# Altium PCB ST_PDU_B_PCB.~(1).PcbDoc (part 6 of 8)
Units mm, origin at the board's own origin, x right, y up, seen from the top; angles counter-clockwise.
Board outline 200 x 200 mm, 6 copper layers (Top Layer, Layer 1, Layer 2, Layer 3, Layer 4, Bottom Layer), stack 3.194 mm thick; 894 components, 723 nets, 3233 pads, 4067 vias.
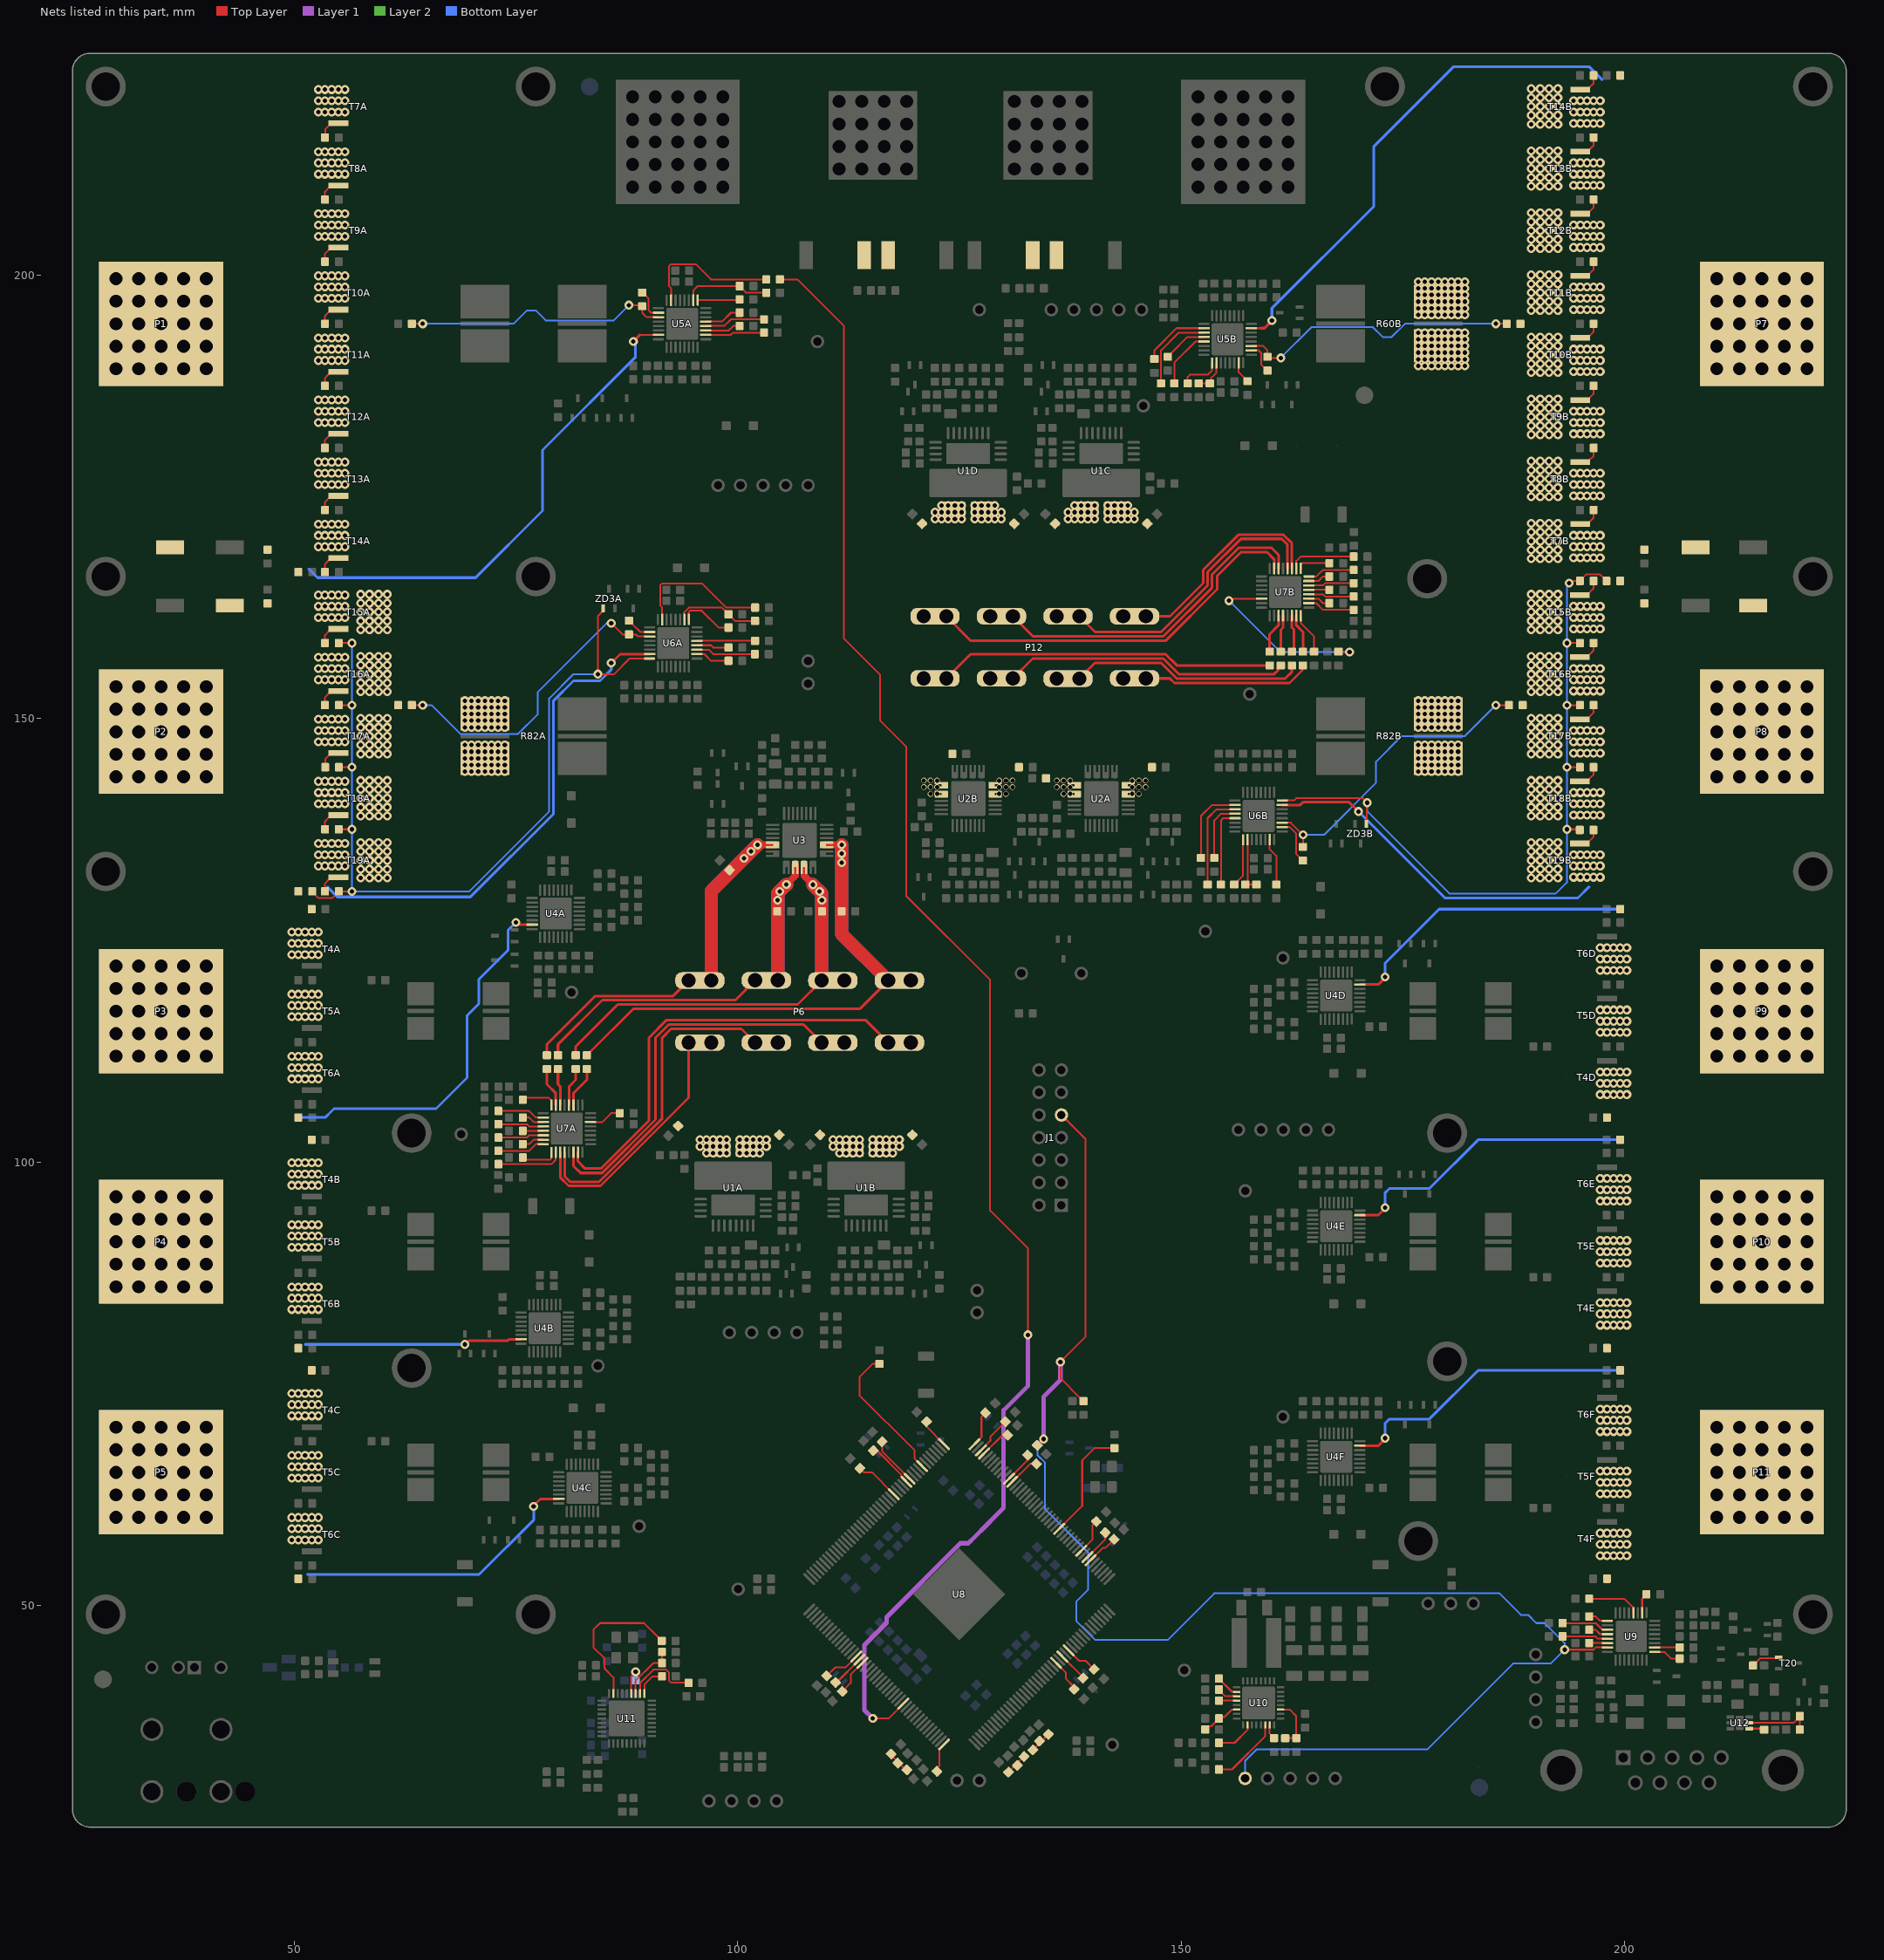
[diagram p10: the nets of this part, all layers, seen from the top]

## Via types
v1: diameter 0.65/1/1/1/1/0.65 (per signal layer), hole 0.5, Top Layer to Bottom Layer, 3739 vias
v2: diameter 0.65/1/1/1/1/0.65 (per signal layer), hole 0.5, Top Layer to Bottom Layer, tented both sides, 296 vias
v3: diameter 0.65, hole 0.5, Top Layer to Bottom Layer, 32 vias

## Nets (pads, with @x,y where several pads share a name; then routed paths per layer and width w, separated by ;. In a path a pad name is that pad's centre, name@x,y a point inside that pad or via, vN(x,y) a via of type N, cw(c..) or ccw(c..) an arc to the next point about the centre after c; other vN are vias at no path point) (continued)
NetR60B_1: R60B.1 R73B.2 T7B.D T8B.D T9B.D T10B.D T11B.D T12B.D T13B.D T14B.D
  other v1: 189.5,168 190.5,168 191.5,168 192.5,168 189.5,169 190.5,169 191.5,169 192.5,169 189.5,170 190.5,170 191.5,170 192.5,170 189.5,171 190.5,171 191.5,171 192.5,171 189.5,172 190.5,172 191.5,172 192.5,172 189.5,175 190.5,175 191.5,175 192.5,175 189.5,176 190.5,176 191.5,176 192.5,176 189.5,177 190.5,177 191.5,177 192.5,177 189.5,178 190.5,178 191.5,178 192.5,178 189.5,179 190.5,179 191.5,179 192.5,179 189.5,182 190.5,182 191.5,182 192.5,182 189.5,183 190.5,183 191.5,183 192.5,183 189.5,184 190.5,184 191.5,184 192.5,184 189.5,185 190.5,185 191.5,185 192.5,185 189.5,186 190.5,186 191.5,186 192.5,186 189.5,189 190.5,189 191.5,189 192.5,189 189.5,190 190.5,190 191.5,190 192.5,190 176.75,190.5 177.5,190.5 178.25,190.5 179,190.5 179.75,190.5 180.5,190.5 181.25,190.5 189.5,191 190.5,191 191.5,191 192.5,191 176.75,191.25 177.5,191.25 178.25,191.25 179,191.25 179.75,191.25 180.5,191.25 181.25,191.25 176.75,192 177.5,192 178.25,192 179,192 179.75,192 180.5,192 181.25,192 189.5,192 190.5,192 191.5,192 192.5,192 176.75,192.75 177.5,192.75 178.25,192.75 179,192.75 179.75,192.75 180.5,192.75 181.25,192.75 189.5,193 190.5,193 191.5,193 192.5,193 176.75,193.5 177.5,193.5 178.25,193.5 179,193.5 179.75,193.5 180.5,193.5 181.25,193.5 176.75,195.5 177.5,195.5 178.25,195.5 179,195.5 179.75,195.5 180.5,195.5 181.25,195.5 189.5,196 190.5,196 191.5,196 192.5,196 176.75,196.25 177.5,196.25 178.25,196.25 179,196.25 179.75,196.25 180.5,196.25 181.25,196.25 176.75,197 177.5,197 178.25,197 179,197 179.75,197 180.5,197 181.25,197 189.5,197 190.5,197 191.5,197 192.5,197 176.75,197.75 177.5,197.75 178.25,197.75 179,197.75 179.75,197.75 180.5,197.75 181.25,197.75 189.5,198 190.5,198 191.5,198 192.5,198 176.75,198.5 177.5,198.5 178.25,198.5 179,198.5 179.75,198.5 180.5,198.5 181.25,198.5 189.5,199 190.5,199 191.5,199 192.5,199 189.5,200 190.5,200 191.5,200 192.5,200 189.5,203 190.5,203 191.5,203 192.5,203 189.5,204 190.5,204 191.5,204 192.5,204 189.5,205 190.5,205 191.5,205 192.5,205 189.5,206 190.5,206 191.5,206 192.5,206 189.5,207 190.5,207 191.5,207 192.5,207 189.5,210 190.5,210 191.5,210 192.5,210 189.5,211 190.5,211 191.5,211 192.5,211 189.5,212 190.5,212 191.5,212 192.5,212 189.5,213 190.5,213 191.5,213 192.5,213 189.5,214 190.5,214 191.5,214 192.5,214 189.5,217 190.5,217 191.5,217 192.5,217 189.5,218 190.5,218 191.5,218 192.5,218 189.5,219 190.5,219 191.5,219 192.5,219 189.5,220 190.5,220 191.5,220 192.5,220 189.5,221 190.5,221 191.5,221 192.5,221
  other v2: 176.75,189.75 177.5,189.75 178.25,189.75 179,189.75 179.75,189.75 180.5,189.75 181.25,189.75 182,189.75 182,190.5 182,191.25 182,192 182,192.75 182,193.5 182,195.5 182,196.25 182,197 182,197.75 182,198.5 176.75,199.25 177.5,199.25 178.25,199.25 179,199.25 179.75,199.25 180.5,199.25 181.25,199.25 182,199.25
NetR61A_2: R61A.2 T7A.G | length 2.7
  Top Layer w0.2: R61A.2@53.475,215.5 53.5,215.525 53.5,216.417 54.178,217.095 T7A.G@54.978,217.095
NetR61B_2: R61B.2 T7B.G | length 2.7
  Top Layer w0.2: T7B.G@195.022,171.905 195.822,171.905 196.5,172.583 196.5,173.475 R61B.2@196.525,173.5
NetR62A_2: R62A.2 T8A.G | length 2.7
  Top Layer w0.2: R62A.2@53.475,208.5 53.475,209.392 53.953,209.87 54.178,210.095 T8A.G@54.978,210.095
NetR62B_2: R62B.2 T8B.G | length 2.7
  Top Layer w0.2: T8B.G@195.022,178.905 195.822,178.905 196.047,179.13 196.525,179.608 R62B.2@196.525,180.5
NetR63A_2: R63A.2 T9A.G | length 2.6
  Top Layer w0.2: R63A.2@53.475,201.5 53.475,202.392 53.953,202.87 54.083,203 T9A.G@54.883,203
NetR63B_2: R63B.2 T9B.G | length 2.6
  Top Layer w0.2: T9B.G@195.117,186 195.917,186 196.047,186.13 196.525,186.608 R63B.2@196.525,187.5
NetR65_1: R65.1 U10.22 | length 8.1
  Top Layer w0.2: R65.1@154.275,31.5 155.75,31.5 159.5,35.25 U10.22@159.5,36.523
NetR66A_2: R66A.2 T10A.G | length 2.8
  Top Layer w0.2: R66A.2@53.475,194.5 53.475,195.392 53.703,195.62 54.178,196.095 T10A.G@54.978,196.095 T10A.G@54.883,196
NetR66B_2: R66B.2 T10B.G | length 2.8
  Top Layer w0.2: T10B.G@195.117,193 T10B.G@195.022,192.905 195.822,192.905 196.297,193.38 196.525,193.608 R66B.2@196.525,194.5
NetR67A_1: R67A.1 U5A.2 | length 6.7
  Top Layer w0.2: U5A.2@96.402,193.25 99.25,193.25 99.5,193.5 R67A.1@102.975,193.5
NetR67B_1: R67B.1 U5B.2 | length 7.4
  Top Layer w0.2: R67B.1@147,190.775 147,191.5 149.5,194 U5B.2@152.598,194
NetR68A_1: R68A.1 U5A.3 | length 4
  Top Layer w0.2: U5A.3@96.402,193.75 99,193.75 99.5,194.25 R68A.1@100.225,194.25
NetR68B_1: R68B.1 U5B.3 | length 9.4
  Top Layer w0.2: R68B.1@147.75,187.775 147.75,191.5 149.75,193.5 U5B.3@152.598,193.5
NetR69A_2: R69A.2 U5A.4 | length 6.9
  Top Layer w0.2: U5A.4@96.402,194.25 98.5,194.25 99.25,195 R69A.2@102.975,195
NetR69B_2: R69B.2 U5B.4 | length 5
  Top Layer w0.2: R69B.2@148.5,190.775 148.518,190.775 148.867,191.124 148.867,191.142 150.725,193 U5B.4@152.598,193
NetR70A_1: R70A.1 U5A.5 | length 4.2
  Top Layer w0.2: U5A.5@96.402,194.75 98.25,194.75 99.25,195.75 R70A.1@100.225,195.75
NetR70B_1: R70B.1 U5B.5 | length 6.7
  Top Layer w0.2: R70B.1@149.25,187.775 149.25,190.102 151.648,192.5 U5B.5@152.598,192.5
NetR72A_2: R72A.2 T11A.G | length 2.7
  Top Layer w0.2: R72A.2@53.475,187.5 53.475,188.392 53.703,188.62 54.178,189.095 T11A.G@54.978,189.095
NetR72B_2: R72B.2 T11B.G | length 2.7
  Top Layer w0.2: T11B.G@195.022,199.905 195.822,199.905 196.297,200.38 196.525,200.608 R72B.2@196.525,201.5
NetR73A_1: R73A.1 R76A.2 U5A.19 | length 30.6
  Top Layer w0.2: R73A.1@63.275,194.5 v1(64.5,194.5) ; v1(87.75,196.6) 89.125,196.6 R76A.2@89.25,196.475 89.25,195.75 89.75,195.25 U5A.19@91.098,195.25
  Bottom Layer w0.2: v1(64.5,194.5) 74.75,194.5 76.25,196 77.25,196 78.371,194.879 86.029,194.879 v1(87.75,196.6)
NetR73B_1: R73B.1 R76B.2 U5B.19 | length 32.5
  Top Layer w0.2: U5B.19@157.902,192 159.25,192 159.75,191.5 R76B.2@159.75,190.775 159.875,190.65 v1(161.25,190.65) ; v1(185.5,194.5) R73B.1@186.725,194.5
  Bottom Layer w0.2: v1(161.25,190.65) 164.721,194.121 171.629,194.121 172.75,193 173.75,193 175.25,194.5 v1@185.718,194.5
NetR74A_2: R74A.2 T12A.G | length 2.6
  Top Layer w0.2: R74A.2@53.475,180.5 53.475,181.392 54.083,182 T12A.G@54.883,182
NetR74B_2: R74B.2 T12B.G | length 2.6
  Top Layer w0.2: T12B.G@195.117,207 195.917,207 196.525,207.608 R74B.2@196.525,208.5
NetR75A_2: R75A.2 R78A.1 U5A.10 | length 9.8
  Top Layer w0.2: U5A.10@95,197.152 95,198.25 95.5,198.75 R75A.2@100.225,198.75 ; R75A.2@100.225,198.725 100.925,198.025 103.2,198.025 R78A.1@103.225,198
NetR75B_2: R75B.2 R78B.1 U5B.10 | length 3.9
  Top Layer w0.2: R75B.2@152,187.775 153.025,187.775 R78B.1@153.25,187.775 153.408,187.933 153.408,188.408 154,189 U5B.10@154,190.098
NetR76A_1: R76A.1 U5A.18 | length 3.6
  Top Layer w0.2: R76A.1@89.25,198.025 89.275,198.025 89.975,197.325 89.975,196.025 90.25,195.75 U5A.18@91.098,195.75
NetR76B_1: R76B.1 U5B.18 | length 3.6
  Top Layer w0.2: U5B.18@157.902,191.5 158.75,191.5 159.025,191.225 159.025,189.925 159.725,189.225 R76B.1@159.75,189.225
NetR77A_1: R77A.1 U5A.9 | length 4.7
  Top Layer w0.2: U5A.9@95.5,197.177 R77A.1@100.225,197.177
NetR77B_1: R77B.1 U5B.9 | length 4.6
  Top Layer w0.2: R77B.1@150.75,187.775 150.75,188.5 151,188.75 153,188.75 153.5,189.25 U5B.9@153.5,190.073
NetR79A_2: R79A.2 T13A.G | length 2.8
  Top Layer w0.2: R79A.2@53.475,173.5 53.475,174.392 53.703,174.62 54.178,175.095 T13A.G@54.978,175.095 T13A.G@54.883,175
NetR79B_2: R79B.2 T13B.G | length 2.8
  Top Layer w0.2: T13B.G@195.117,214 T13B.G@195.022,213.905 195.822,213.905 196.297,214.38 196.525,214.608 R79B.2@196.525,215.5
NetR80A_1: R80A.1 U5A.15 | length 15.7
  Top Layer w0.2: U5A.15@92.5,197.152 92.5,198.512 92.275,198.737 92.275,201.013 92.487,201.225 95.275,201.225 97,199.5 R80A.1@103.225,199.5
NetR80B_1: R80B.1 U5B.15 | length 2.5
  Top Layer w0.2: U5B.15@156.5,190.098 156.5,189.025 157.133,188.392 157.133,188.374 157.482,188.025 R80B.1@157.5,188.025
NetR81A_2: R81A.2 T14A.G | length 2.8
  Top Layer w0.2: R81A.2@53.475,166.5 53.475,167.392 53.703,167.62 54.178,168.095 54.883,168.095 T14A.G@54.978,168.095 T14A.G@54.883,168
NetR81B_2: R81B.2 T14B.G | length 2.8
  Top Layer w0.2: T14B.G@195.117,221 T14B.G@195.022,220.905 195.117,220.905 195.822,220.905 196.297,221.38 196.525,221.608 R81B.2@196.525,222.5
NetR82A_1: R82A.1 R93A.2 T15A.D T16A.D T17A.D T18A.D T19A.D
  other v1: 57.5,132 58.5,132 59.5,132 60.5,132 57.5,133 58.5,133 59.5,133 60.5,133 57.5,134 58.5,134 59.5,134 60.5,134 57.5,135 58.5,135 59.5,135 60.5,135 57.5,136 58.5,136 59.5,136 60.5,136 57.5,139 58.5,139 59.5,139 60.5,139 57.5,140 58.5,140 59.5,140 60.5,140 57.5,141 58.5,141 59.5,141 60.5,141 57.5,142 58.5,142 59.5,142 60.5,142 57.5,143 58.5,143 59.5,143 60.5,143 69.25,144 70,144 70.75,144 71.5,144 72.25,144 73,144 73.75,144 69.25,144.75 70,144.75 70.75,144.75 71.5,144.75 72.25,144.75 73,144.75 73.75,144.75 69.25,145.5 70,145.5 70.75,145.5 71.5,145.5 72.25,145.5 73,145.5 73.75,145.5 57.5,146 58.5,146 59.5,146 60.5,146 69.25,146.25 70,146.25 70.75,146.25 71.5,146.25 72.25,146.25 73,146.25 73.75,146.25 57.5,147 58.5,147 59.5,147 60.5,147 69.25,147 70,147 70.75,147 71.5,147 72.25,147 73,147 73.75,147 57.5,148 58.5,148 59.5,148 60.5,148 57.5,149 58.5,149 59.5,149 60.5,149 69.25,149 70,149 70.75,149 71.5,149 72.25,149 73,149 73.75,149 69.25,149.75 70,149.75 70.75,149.75 71.5,149.75 72.25,149.75 73,149.75 73.75,149.75 57.5,150 58.5,150 59.5,150 60.5,150 69.25,150.5 70,150.5 70.75,150.5 71.5,150.5 72.25,150.5 73,150.5 73.75,150.5 69.25,151.25 70,151.25 70.75,151.25 71.5,151.25 72.25,151.25 73,151.25 73.75,151.25 69.25,152 70,152 70.75,152 71.5,152 72.25,152 73,152 73.75,152 57.5,153 58.5,153 59.5,153 60.5,153 57.5,154 58.5,154 59.5,154 60.5,154 57.5,155 58.5,155 59.5,155 60.5,155 57.5,156 58.5,156 59.5,156 60.5,156 57.5,157 58.5,157 59.5,157 60.5,157 57.5,160 58.5,160 59.5,160 60.5,160 57.5,161 58.5,161 59.5,161 60.5,161 57.5,162 58.5,162 59.5,162 60.5,162 57.5,163 58.5,163 59.5,163 60.5,163 57.5,164 58.5,164 59.5,164 60.5,164
NetR82B_1: R82B.1 R93B.2 T15B.D T16B.D T17B.D T18B.D T19B.D
  other v1: 189.5,132 190.5,132 191.5,132 192.5,132 189.5,133 190.5,133 191.5,133 192.5,133 189.5,134 190.5,134 191.5,134 192.5,134 189.5,135 190.5,135 191.5,135 192.5,135 189.5,136 190.5,136 191.5,136 192.5,136 189.5,139 190.5,139 191.5,139 192.5,139 189.5,140 190.5,140 191.5,140 192.5,140 189.5,141 190.5,141 191.5,141 192.5,141 189.5,142 190.5,142 191.5,142 192.5,142 189.5,143 190.5,143 191.5,143 192.5,143 176.75,144 177.5,144 178.25,144 179,144 179.75,144 180.5,144 181.25,144 176.75,144.75 177.5,144.75 178.25,144.75 179,144.75 179.75,144.75 180.5,144.75 181.25,144.75 176.75,145.5 177.5,145.5 178.25,145.5 179,145.5 179.75,145.5 180.5,145.5 181.25,145.5 189.5,146 190.5,146 191.5,146 192.5,146 176.75,146.25 177.5,146.25 178.25,146.25 179,146.25 179.75,146.25 180.5,146.25 181.25,146.25 176.75,147 177.5,147 178.25,147 179,147 179.75,147 180.5,147 181.25,147 189.5,147 190.5,147 191.5,147 192.5,147 189.5,148 190.5,148 191.5,148 192.5,148 176.75,149 177.5,149 178.25,149 179,149 179.75,149 180.5,149 181.25,149 189.5,149 190.5,149 191.5,149 192.5,149 176.75,149.75 177.5,149.75 178.25,149.75 179,149.75 179.75,149.75 180.5,149.75 181.25,149.75 189.5,150 190.5,150 191.5,150 192.5,150 176.75,150.5 177.5,150.5 178.25,150.5 179,150.5 179.75,150.5 180.5,150.5 181.25,150.5 176.75,151.25 177.5,151.25 178.25,151.25 179,151.25 179.75,151.25 180.5,151.25 181.25,151.25 176.75,152 177.5,152 178.25,152 179,152 179.75,152 180.5,152 181.25,152 189.5,153 190.5,153 191.5,153 192.5,153 189.5,154 190.5,154 191.5,154 192.5,154 189.5,155 190.5,155 191.5,155 192.5,155 189.5,156 190.5,156 191.5,156 192.5,156 189.5,157 190.5,157 191.5,157 192.5,157 189.5,160 190.5,160 191.5,160 192.5,160 189.5,161 190.5,161 191.5,161 192.5,161 189.5,162 190.5,162 191.5,162 192.5,162 189.5,163 190.5,163 191.5,163 192.5,163 189.5,164 190.5,164 191.5,164 192.5,164
NetR83A_1: R83A.1 R84A.1 R86A.1 R92A.1 R95A.1 R100A.1 U6A.24 ZD3A.1 | length 98.5
  Top Layer w0.2: R84A.1@52.025,130.5 52.025,130.475 52.725,129.775 54.325,129.775 55.025,130.475 R100A.1@55.025,130.5 v1(56.5,130.5) ; R95A.1@55.025,137.5 v1(56.5,137.5) ; R86A.1@55.025,151.5 v1(56.5,151.5) ; R83A.1@55.025,158.5 v1(56.5,158.5) ; R92A.1@55.05,144.5 v1(56.5,144.5) ; ZD3A.1@84.85,162.392 84.85,162.159 84.25,161.559 v1(84.25,155) 86.085,155 87.835,156.75 U6A.24@90.073,156.75
  Bottom Layer w0.2: v1(56.5,158.5) v1(56.5,151.5) v1(56.5,144.5) v1(56.5,137.5) v1(56.5,130.5) 69.75,130.5 78.75,139.5 78.75,152.25 81.5,155 v1(84.25,155)
NetR83A_2: R83A.2 T15A.G | length 2.7
  Top Layer w0.2: R83A.2@53.475,158.5 53.475,159.392 53.953,159.87 54.178,160.095 T15A.G@54.978,160.095
NetR83B_1: R83B.1 R84B.1 R86B.1 R92B.1 R95B.1 R100B.1 U6B.24 ZD3B.1 | length 84.9
  Top Layer w0.2: U6B.24@161.427,140.75 162.75,140.75 163,141 170.5,141 v1(171,140.5) 170.95,140.45 170.95,138.158 ZD3B.1@170.9,138.108 ; v1(193.5,137.5) 194.884,137.5 R100B.1@194.961,137.423 ; v1(193.5,144.5) R95B.1@194.975,144.5 ; v1(193.5,151.5) R92B.1@194.975,151.5 ; v1(193.5,158.5) R86B.1@194.975,158.5 ; v1(193.75,165.25) 193.872,165.25 194.122,165.5 R83B.1@194.975,165.5 194.975,165.525 195.675,166.225 197.275,166.225 197.975,165.525 R84B.1@197.975,165.5
  Bottom Layer w0.2: v1(171,140.5) 171,139.5 180.25,130.25 192.25,130.25 192.5,130.5 193.5,131.5 v1(193.5,137.5) v1(193.5,144.5) v1(193.5,151.5) v1(193.5,158.5) 193.5,164.908 193.75,165.158 v1(193.75,165.25)
NetR83B_2: R83B.2 T15B.G | length 2.7
  Top Layer w0.2: T15B.G@194.972,163.905 195.772,163.905 196.5,164.633 196.5,165.475 R83B.2@196.525,165.5
NetR85_1: R85.1 U9.10 | length 2.3
  Top Layer w0.2: U9.10@202,49.152 202,50.743 202.475,51.218 R85.1@202.475,51.25
NetR86A_2: R86A.2 T16A.G | length 2.7
  Top Layer w0.2: R86A.2@53.475,151.5 53.475,152.392 53.953,152.87 54.178,153.095 T16A.G@54.978,153.095
NetR86B_2: R86B.2 T16B.G | length 2.7
  Top Layer w0.2: T16B.G@194.972,156.905 195.772,156.905 196.5,157.633 196.5,158.475 R86B.2@196.525,158.5
NetR87A_1: R87A.1 U6A.2 | length 3.9
  Top Layer w0.2: U6A.2@95.402,157.25 96.25,157.25 97,156.5 R87A.1@98.975,156.5
NetR87B_1: R87B.1 U6B.2 | length 9.1
  Top Layer w0.2: R87B.1@152.25,134.275 152.25,139 153.5,140.25 U6B.2@156.098,140.25
NetR88A_1: R88A.1 U6A.3 | length 6.8
  Top Layer w0.2: U6A.3@95.402,157.75 96.75,157.75 97.25,157.25 R88A.1@101.95,157.25
NetR88B_1: R88B.1 U6B.3 | length 11
  Top Layer w0.2: R88B.1@153,131.275 153,138.75 154,139.75 U6B.3@156.098,139.75
NetR89A_2: R89A.2 U6A.4 | length 3.7
  Top Layer w0.2: U6A.4@95.402,158.25 97,158.25 97.25,158 R89A.2@98.975,158
NetR89B_2: R89B.2 U6B.4 | length 6.9
  Top Layer w0.2: R89B.2@153.75,134.275 153.75,138.5 154.5,139.25 U6B.4@156.098,139.25
NetR90A_1: R90A.1 U6A.5 | length 6.6
  Top Layer w0.2: U6A.5@95.402,158.75 R90A.1@101.975,158.75
NetR90B_1: R90B.1 U6B.5 | length 8.9
  Top Layer w0.2: R90B.1@154.5,131.275 154.5,138.5 154.75,138.75 U6B.5@156.098,138.75
NetR91_2: R91.2 U10.23 | length 1.7
  Top Layer w0.2: U10.23@160,36.523 160,35.525 160.133,35.392 160.133,35.374 160.482,35.025 R91.2@160.5,35.025
NetR92A_2: R92A.2 T17A.G | length 2.7
  Top Layer w0.2: R92A.2@53.5,144.5 53.5,145.417 54.178,146.095 T17A.G@54.978,146.095
NetR92B_2: R92B.2 T17B.G | length 2.7
  Top Layer w0.2: T17B.G@194.972,149.905 195.772,149.905 196.5,150.633 196.5,151.475 R92B.2@196.525,151.5
NetR93A_1: R93A.1 R96A.2 U6A.19 | length 35.4
  Top Layer w0.2: R93A.1@63.275,151.5 v1(64.5,151.5) ; v1(85.75,160.75) 87.025,159.475 88.525,159.475 88.75,159.25 U6A.19@90.098,159.25
  Bottom Layer w0.2: v1(64.5,151.5) 65.5,151.5 68.75,148.25 75.25,148.25 77.446,150.446 77.446,152.946 85.25,160.75 v1(85.75,160.75)
NetR93B_1: R93B.1 R96B.2 U6B.19 | length 34.9
  Top Layer w0.2: U6B.19@161.402,138.25 162.377,138.25 v1(163.75,136.877) R96B.2@163.75,135.525 ; v1(185.5,151.5) R93B.1@186.975,151.5
  Bottom Layer w0.2: v1(163.75,136.877) 166.127,136.877 172,142.75 172,145.133 174.867,148 182,148 v1(185.5,151.5)
NetR94A_2: R94A.2 R98A.1 U6A.10 | length 9.7
  Top Layer w0.2: U6A.10@94,161.152 94,162 94.5,162.5 98.225,162.5 98.608,162.117 98.626,162.117 98.975,161.768 R94A.2@98.975,161.75 98.975,161.732 99.324,161.383 99.342,161.383 99.725,161 R98A.1@101.975,161
NetR94B_2: R94B.2 R98B.1 U6B.10 | length 6.4
  Top Layer w0.2: U6B.10@157.5,136.348 157.5,131.525 R98B.1@157.25,131.275 R94B.2@158.5,131.275
NetR95A_2: R95A.2 T18A.G | length 2.7
  Top Layer w0.2: R95A.2@53.475,137.5 53.475,138.392 53.953,138.87 54.178,139.095 T18A.G@54.978,139.095
NetR95B_2: R95B.2 T18B.G | length 2.7
  Top Layer w0.2: T18B.G@194.972,142.905 195.772,142.905 196.5,143.633 196.5,144.475 R95B.2@196.525,144.5
NetR96A_1: R96A.1 U6A.18 | length 2.9
  Top Layer w0.2: R96A.1@87.75,161.025 87.768,161.025 88.117,160.676 88.117,160.658 89.025,159.75 U6A.18@90.098,159.75
NetR96B_1: R96B.1 U6B.18 | length 5.3
  Top Layer w0.2: U6B.18@161.402,137.75 162.25,137.75 163,137 163,134.699 163.724,133.974 R96B.1@163.749,133.974
NetR97A_1: R97A.1 U6A.9 | length 6.1
  Top Layer w0.2: U6A.9@94.5,161.177 94.5,162 94.65,162.15 95.954,162.15 97.854,160.25 R97A.1@98.975,160.25
NetR97B_1: R97B.1 U6B.9 | length 5.5
  Top Layer w0.2: R97B.1@156,131.275 157,132.275 U6B.9@157,136.323
NetR99A_1: R99A.1 U6A.15 | length 15.9
  Top Layer w0.2: U6A.15@91.5,161.152 91.5,162.512 91.275,162.737 91.275,165.013 91.487,165.225 95.995,165.225 98.72,162.5 R99A.1@101.975,162.5
NetR99B_1: R99B.1 U6B.15 | length 5.4
  Top Layer w0.2: U6B.15@160,136.348 160,135.25 160.75,134.5 R99B.1@160.75,131.275
NetR100A_2: R100A.2 T19A.G | length 2.7
  Top Layer w0.2: R100A.2@53.475,130.5 53.475,131.392 53.953,131.87 54.178,132.095 T19A.G@54.978,132.095
NetR100B_2: R100B.2 T19B.G | length 2.6
  Top Layer w0.2: T19B.G@194.972,135.905 195.772,135.905 196.5,136.633 196.5,137.412 R100B.2@196.511,137.423
NetR102A_1: R102A.1 U7A.32 | length 4
  Top Layer w0.2: R102A.1@75.775,107 76.025,107.25 78.675,107.25 79,106.925 U7A.32@79,106.427
NetR102B_1: R102B.1 U7B.32 | length 4.7
  Top Layer w0.2: U7B.32@163.5,161.573 163.5,160.75 165,159.25 R102B.1@165,157.525
NetR103A_1: R103A.1 U7A.7 | length 2.5
  Top Layer w0.2: R103A.1@75.775,102 76.5,102 77,102.5 U7A.7@78.098,102.5
NetR103B_1: R103B.1 U7B.7 | length 2.5
  Top Layer w0.2: U7B.7@164.402,165.5 165.5,165.5 166,166 R103B.1@166.725,166
NetR104A_1: R104A.1 U7A.8 | length 5.4
  Top Layer w0.2: R104A.1@73.025,101.25 76.5,101.25 77.25,102 U7A.8@78.073,102
NetR104B_1: R104B.1 U7B.8 | length 5.4
  Top Layer w0.2: U7B.8@164.427,166 165.25,166 166,166.75 R104B.1@169.475,166.75
NetR105A_1: R105A.1 U7A.9 | length 4.1
  Top Layer w0.2: R105A.1@75.775,100.5 76.025,100.25 78.855,100.25 78.973,100.367 78.973,101.046 U7A.9@79,101.073
NetR105B_1: R105B.1 U7B.9 | length 3.8
  Top Layer w0.2: U7B.9@163.5,166.927 163.5,167.425 163.527,167.452 163.597,167.452 163.645,167.5 R105B.1@166.725,167.5
NetR106A_1: R106A.1 U7A.10 | length 7.5
  Top Layer w0.2: R106A.1@73.025,99.75 79,99.75 79.5,100.25 U7A.10@79.5,101.098
NetR106B_1: R106B.1 U7B.10 | length 7.5
  Top Layer w0.2: U7B.10@163,166.902 163,167.75 163.5,168.25 R106B.1@169.475,168.25
NetR107A_1: R107A.1 U7A.3 | length 2.5
  Top Layer w0.2: R107A.1@75.775,105 76.5,105 77,104.5 U7A.3@78.098,104.5
NetR107B_1: R107B.1 U7B.3 | length 2.5
  Top Layer w0.2: U7B.3@164.402,163.5 165.5,163.5 166,163 R107B.1@166.725,163
NetR108A_1: R108A.1 U7A.6 | length 5.2
  Top Layer w0.2: R108A.1@73.025,102.75 76.238,102.75 76.488,103 U7A.6@78.098,103
NetR108B_1: R108B.1 U7B.6 | length 5.2
  Top Layer w0.2: U7B.6@164.402,165 166.012,165 166.262,165.25 R108B.1@169.475,165.25
NetR109A_1: R109A.1 U7A.4 | length 5.2
  Top Layer w0.2: R109A.1@73.025,104.25 76.238,104.25 76.488,104 U7A.4@78.098,104
NetR109B_1: R109B.1 U7B.4 | length 5.2
  Top Layer w0.2: U7B.4@164.402,164 166.012,164 166.262,163.75 R109B.1@169.475,163.75
NetR110A_1: R110A.1 U7A.5 | length 2.3
  Top Layer w0.2: R110A.1@75.775,103.5 U7A.5@78.098,103.5
NetR110B_1: R110B.1 U7B.5 | length 2.3
  Top Layer w0.2: U7B.5@164.402,164.5 R110B.1@166.725,164.5
NetR111_2: R111.2 U7A.27 | length 4.7
  Top Layer w0.3: U7A.27@81.5,106.402 81.5,107.75 83,109.25 R111.2@83,110.475
NetR112_2: R112.2 U7A.28 | length 4.4
  Top Layer w0.3: U7A.28@81,106.402 81,108.5 81.75,109.25 R112.2@81.75,110.475
NetR113_2: R113.2 U7A.30 | length 4.2
  Top Layer w0.3: R113.2@79.75,110.475 79.75,108.75 80,108.5 U7A.30@80,106.402
NetR114_2: R114.2 U7A.31 | length 4.5
  Top Layer w0.3: R114.2@78.5,110.475 78.5,108.75 79.5,107.75 U7A.31@79.5,106.402
NetR115_2: R115.2 U7B.27 | length 4.5
  Top Layer w0.3: R115.2@160,157.525 160,159.5 161,160.5 U7B.27@161,161.598
NetR116_2: R116.2 U7B.28 | length 4.2
  Top Layer w0.3: R116.2@161.25,157.525 161.25,160 161.5,160.25 U7B.28@161.5,161.598
NetR117_2: R117.2 U7B.30 | length 4.3
  Top Layer w0.3: R117.2@162.5,157.525 162.75,157.775 162.75,160 162.5,160.25 U7B.30@162.5,161.598
NetR118_2: R118.2 U7B.31 | length 4.4
  Top Layer w0.3: U7B.31@163,161.598 163,160.5 163.75,159.75 R118.2@163.75,157.525
NetR119_1: R119.1 U8.149 | length 5
  Top Layer w0.2: R119.1@113.798,65.452 114.25,65 115.139,65 U8.149@117.621,62.518
NetR120_1: R120.1 U8.145 | length 5.3
  Top Layer w0.2: R120.1@115.298,67.452 115.728,67.452 118.459,64.721 118.459,64.536 119.036,63.959 U8.145@119.036,63.932
NetR121_1: R121.1 U8.144 | length 5.5
  Top Layer w0.2: R121.1@116.298,68.452 116.285,68.439 116.285,67.945 116.298,67.933 116.298,67.377 U8.144@119.389,64.286
NetR123_1: R123.1 U8.133 | length 3.4
  Top Layer w0.2: R123.1@121.298,70.702 121.285,70.689 121.285,70.175 U8.133@123.278,68.181
NetR124_1: R124.1 U8.132 | length 4
  Top Layer w0.2: U8.132@126.722,68.175 127.5,68.953 127.5,71.25 R124.1@127.952,71.702
NetR125_1: R125.1 U8.130 | length 4.4
  Top Layer w0.2: U8.130@127.429,67.467 128.5,68.539 128.5,69 R125.1@130.202,70.702
NetR126_1: R126.1 U8.129 | length 3.5
  Top Layer w0.2: U8.129@127.782,67.114 129.883,69.215 130.439,69.215 R126.1@130.452,69.202
NetR129_1: R129.1 U8.121 | length 3.5
  Top Layer w0.2: U8.121@130.611,64.286 132.715,66.39 132.715,66.939 R129.1@132.702,66.952
NetR130_1: R130.1 U8.120 | length 3.6
  Top Layer w0.2: U8.120@130.964,63.932 132.997,65.965 133.689,65.965 R130.1@133.702,65.952
NetR131_2: R131.2 U8.16 | length 4.2
  Top Layer w0.2: R131.2@110.048,42.048 111,43 112.154,43 U8.16@113.379,44.225
NetR132_2: R132.2 U8.17 | length 3.7
  Top Layer w0.2: R132.2@111.103,41.243 U8.17@113.732,43.871
NetR133_2: R133.2 U8.18 | length 4.2
  Top Layer w0.2: R133.2@111.798,40.298 112.75,41.25 112.75,42.182 U8.18@114.086,43.518
NetR135_1: R135.1 U8.98 | length 4
  Top Layer w0.2: U8.98@138.743,56.154 140,57.411 140,59 R135.1@140.452,59.452
NetR136_1: R136.1 U8.96 | length 3.6
  Top Layer w0.2: U8.96@139.45,55.447 141.452,57.449 R136.1@141.452,58.202
NetR137_1: R137.1 U8.95 | length 3.6
  Top Layer w0.2: U8.95@139.803,55.093 141.21,56.5 141.5,56.5 R137.1@142.452,57.452
NetR139_1: R139.1 U8.71 | length 3.6
  Top Layer w0.2: U8.71@135.914,43.518 137,42.432 137,41.75 R139.1@137.952,40.798
NetR140_1: R140.1 U8.73 | length 3.4
  Top Layer w0.2: U8.73@136.621,44.225 138.952,41.894 R140.1@138.952,41.798
NetR141_1: R141.1 U8.75 | length 4
  Top Layer w0.2: U8.75@137.328,44.932 138.51,43.75 139.25,43.75 139.995,43.005 R141.1@139.995,42.513
NetR143_1: R143.1 R146.1 R149.1 | length 2.6
  Top Layer w0.2: R149.1@130.548,31.202 131.298,31.952 R143.1@131.548,31.952 131.548,32.202 R146.1@132.298,32.952
NetR144_1: R144.1 R147.1 R150.1 | length 2.7
  Top Layer w0.2: R147.1@117.308,33.234 117.308,33.107 118.07,32.345 R144.1@118.07,32.218 118.197,32.218 118.959,31.456 R150.1@119.086,31.456
NetR145_1: R145.1 R148.1 R151.1 | length 2.6
  Top Layer w0.2: R151.1@133.298,33.702 134.048,34.452 R145.1@134.048,34.702 134.298,34.702 R148.1@135.048,35.452
NetR152_1: R152.1 U9.12 | length 6.2
  Top Layer w0.2: R152.1@196.025,50.75 200,50.75 200.973,49.777 200.973,49.005 U9.12@201,48.977
NetR153_2: R153.2 U9.17 | length 2.5
  Top Layer w0.2: R153.2@196.025,48.75 196.75,48.75 197.25,48.25 U9.17@198.273,48.25
NetR154_2: R154.2 U9.19 | length 5.4
  Top Layer w0.2: R154.2@193.025,48 193.05,47.975 196.775,47.975 197.5,47.25 U9.19@198.098,47.25
NetR155_2: R155.2 U9.20 | length 2.5
  Top Layer w0.2: R155.2@196.025,47.25 196.75,47.25 197.25,46.75 U9.20@198.273,46.75
NetR156_2: R156.2 R166.1 U10.27 | length 5.8
  Top Layer w0.2: U10.27@161.227,38.25 162.25,38.25 163,37.5 R156.2@163,35.025 R166.1@161.75,35.025
NetR157_2: R157.2 U9.21 | length 5.4
  Top Layer w0.2: R157.2@193.025,46.5 196.75,46.5 197,46.25 U9.21@198.273,46.25
NetR158_2: R158.2 R165.2 U10.14 | length 4.5
  Top Layer w0.2: R158.2@152.725,36 152.725,36.018 153.074,36.367 153.417,36.367 154.275,37.225 R165.2@154.275,37.25 154.433,37.408 154.908,37.408 155.747,38.247 156.269,38.247 U10.14@156.273,38.25
NetR159_1: R159.1 U9.22 | length 2.2
  Top Layer w0.2: R159.1@196.025,45.75 U9.22@198.273,45.75
NetR160_1: R160.1 U9.2 | length 3
  Top Layer w0.2: U9.2@203.227,45.25 R160.1@206.225,45.25
NetR161_1: R161.1 U9.1 | length 3.3
  Top Layer w0.2: U9.1@203.227,44.75 204.5,44.75 205.25,44 R161.1@206.225,44
NetR162_1: R162.1 U10.10 | length 2.6
  Top Layer w0.2: R162.1@154.275,41.75 154.275,41.725 155.747,40.253 156.269,40.253 U10.10@156.273,40.25
NetR163_2: R163.2 U10.11 | length 2.3
  Top Layer w0.2: R163.2@154.275,40.5 154.275,40.475 155,39.75 U10.11@156.273,39.75
NetR164_2: R164.2 U10.12 | length 2
  Top Layer w0.2: R164.2@154.275,39.25 U10.12@156.273,39.25
NetR167_2: R167.2 U10.18 | length 4.4
  Top Layer w0.2: R167.2@154.275,34.5 156.043,34.5 157.5,35.957 U10.18@157.5,36.523
NetR169_2: R169.2 U8.44 | length 3.4
  Top Layer w0.2: R169.2@122.468,31.282 122.468,31.617 122.748,31.897 122.748,33.795 U8.44@123.278,34.325
NetR172_1: R172.1 T20.1 | length 3.3
  Top Layer w0.2: R172.1@214.5,43.225 214.525,43.225 215.347,44.047 217.288,44.047 T20.1@217.392,44.15
NetR182_2: R182.2 R186.2 U11.3 | length 6.1
  Top Layer w0.2: U11.3@88.5,40.45 88.5,41.5 90.5,43.5 R186.2@91.475,43.5 R182.2@91.475,44.75
NetR184_2: R184.2 U11.1 | length 3
  Top Layer w0.2: U11.1@89.5,40.45 89.5,41.062 90.438,42 R184.2@91.475,42
NetR185_2: R185.2 U11.2 | length 8
  Top Layer w0.2: U11.2@89,40.45 89.019,40.469 89.019,41.269 90.5,42.75 91.938,42.75 92.25,42.438 92.25,41.55 92.525,41.275 94.45,41.275 R185.2@94.475,41.25
NetR188_2: R188.2 U11.8 | length 16.6
  Top Layer w0.2: U11.8@86,40.45 86,41.862 85,42.862 85,44 83.75,45.25 83.75,47.25 84.5,48 89.45,48 91.083,46.367 91.101,46.367 91.45,46.018 R188.2@91.45,46
NetR189_2: R189.2 U11.4 | length 3.2
  Top Layer w0.2: U11.4@88,40.45 88,42 v1(88.5,42.5)
  Bottom Layer w0.2: R189.2@88.5,41.525 v1(88.5,42.5)
NetR197A_1: R197A.1 U7A.2 | length 5.4
  Top Layer w0.2: R197A.1@73.025,105.75 76.5,105.75 77.25,105 U7A.2@78.098,105
NetR197B_1: R197B.1 U7B.2 | length 5.4
  Top Layer w0.2: U7B.2@164.402,163 165.25,163 166,162.25 R197B.1@169.475,162.25
NetR198A_1: R198A.1 U7A.22 | length 3.7
  Top Layer w0.2: U7A.22@83.402,104.5 84.75,104.5 85.75,105.5 R198A.1@86.725,105.5
NetR198B_1: R198B.1 U7B.22 | length 21
  Top Layer w0.2: v1(155.413,163.274) 155.535,163.274 155.76,163.5 U7B.22@159.098,163.5 ; R198B.1@167.75,157.525 167.775,157.5 v1(169,157.5)
  Bottom Layer w0.2: v1(155.413,163.274) 161.187,157.5 v1(169,157.5)
NetR199_2: R199.2 R201.2 U12.5 | length 7.5
  Top Layer w0.2: U12.5@214.076,36.75 219.05,36.75 R199.2@219.775,37.475 ; R201.2@219.775,36 R199.2@219.775,37.475 ; R199.2@219.775,37.5 R199.2@219.775,37.475
NetR200_1: R200.1 U12.4 | length 1.7
  Top Layer w0.2: U12.4@214.076,36.1 215.625,36.1 R200.1@215.75,35.975
NetR204_1: R204.1 U8.140 | length 15.6
  Top Layer w0.2: R204.1@115.75,77.25 115.25,77.25 113.75,75.75 113.75,73.672 119.961,67.461 119.961,66.555 120.803,65.712 U8.140@120.803,65.7
NetR205_1: R205.1 U8.105 | length 13
  Top Layer w0.2: U8.105@136.268,58.629 138.86,61.221 138.86,66.36 140.225,67.725 R205.1@142.5,67.725
NetTr_d18_A: Tr_d18.A Tr_d20.A
NetTr_d19_A: Tr_d19.A Tr_d21.A
NRST: J1.9 R127.2 R129.2 R202.1 TP31.1 U9.23 | length 179.5
  Top Layer w0.2: R129.2@133.798,68.048 v1(134.5,68.75) ; J1.9@136.52,105.29 139.25,102.56 139.25,80.302 v1(136.4,77.452) 136.4,75.625 138.633,73.392 138.633,73.374 138.982,73.025 R202.1@139,73.025 ; v1(193.25,45) 196.5,45 196.75,45.25 U9.23@198.098,45.25 U9.23@198.273,45.25
  Layer 1 w0.5: v1(134.5,68.75) 134.5,73.525 136.4,75.425 v1(136.4,77.452)
  Layer 2 w0.5: TP31.1@157.141,30.48 TP31.1@157.226,30.48
  Bottom Layer w0.2: v1(134.5,68.75) R127.2@133.798,68.048 133.816,68.03 133.816,66.934 134.663,66.087 134.663,60.831 139.5,55.993 139.5,51.75 138.175,50.425 138.175,48.262 140.337,46.1 148.5,46.1 153.75,51.35 185.9,51.35 188.325,48.925 189.138,48.925 190.063,48 191,48 193.25,45.75 v1(193.25,45) 191.684,43.434 187.434,43.434 177.75,33.75 158.5,33.75 157.226,32.476 TP31.1@157.226,30.48
OUT_A1: C42A.2 P1.1 R64A.2 T7A.S T8A.S T9A.S T10A.S T11A.S T12A.S T13A.S T14A.S Tr_d3.A U5A.23 | length 56.5
  Top Layer w0.2: 89.009,193.25 U5A.23@91.098,193.25
  Top Layer w0.3: v1(88.253,192.493) 89.009,193.25
  Bottom Layer w0.3: 51.667,166.833 52.625,165.875 70.454,165.875 78,173.421 78,180.25 88.492,190.742 88.492,192.159 88.253,192.399 v1(88.253,192.493)
  other v1: 52.728,169.365 53.478,169.365 54.228,169.365 54.978,169.365 55.728,169.365 52.728,170.635 53.478,170.635 54.228,170.635 54.978,170.635 55.728,170.635 52.728,171.905 53.478,171.905 54.228,171.905 54.978,171.905 55.728,171.905 52.728,176.365 53.478,176.365 54.228,176.365 54.978,176.365 55.728,176.365 52.728,177.635 53.478,177.635 54.228,177.635 54.978,177.635 55.728,177.635 52.728,178.905 53.478,178.905 54.228,178.905 54.978,178.905 55.728,178.905 52.728,183.365 53.478,183.365 54.228,183.365 54.978,183.365 55.728,183.365 52.728,184.635 53.478,184.635 54.228,184.635 54.978,184.635 55.728,184.635 52.728,185.905 53.478,185.905 54.228,185.905 54.978,185.905 55.728,185.905 52.728,190.365 53.478,190.365 54.228,190.365 54.978,190.365 55.728,190.365 52.728,191.635 53.478,191.635 54.228,191.635 54.978,191.635 55.728,191.635 52.728,192.905 53.478,192.905 54.228,192.905 54.978,192.905 55.728,192.905 52.728,197.365 53.478,197.365 54.228,197.365 54.978,197.365 55.728,197.365 52.728,198.635 53.478,198.635 54.228,198.635 54.978,198.635 55.728,198.635 52.728,199.905 53.478,199.905 54.228,199.905 54.978,199.905 55.728,199.905 52.728,204.365 53.478,204.365 54.228,204.365 54.978,204.365 55.728,204.365 52.728,205.635 53.478,205.635 54.228,205.635 54.978,205.635 55.728,205.635 52.728,206.905 53.478,206.905 54.228,206.905 54.978,206.905 55.728,206.905 52.728,211.365 53.478,211.365 54.228,211.365 54.978,211.365 55.728,211.365 52.728,212.635 53.478,212.635 54.228,212.635 54.978,212.635 55.728,212.635 52.728,213.905 53.478,213.905 54.228,213.905 54.978,213.905 55.728,213.905 52.728,218.365 53.478,218.365 54.228,218.365 54.978,218.365 55.728,218.365 52.728,219.635 53.478,219.635 54.228,219.635 54.978,219.635 55.728,219.635 52.728,220.905 53.478,220.905 54.228,220.905 54.978,220.905 55.728,220.905
OUT_A2: C52A.2 P2.1 R84A.2 T15A.S T16A.S T17A.S T18A.S T19A.S Tr_d4.A U6A.23 | length 56.1
  Top Layer w0.3: v1(85.75,156.25) 86.75,157.25 U6A.23@90.098,157.25
  Bottom Layer w0.3: 53.75,131 54.875,129.875 69.875,129.875 79.25,139.25 79.25,152 81.5,154.25 84.5,154.25 85.75,155.5 v1(85.75,156.25)
  other v1: 52.728,133.365 53.478,133.365 54.228,133.365 54.978,133.365 55.728,133.365 52.728,134.635 53.478,134.635 54.228,134.635 54.978,134.635 55.728,134.635 52.728,135.905 53.478,135.905 54.228,135.905 54.978,135.905 55.728,135.905 52.728,140.365 53.478,140.365 54.228,140.365 54.978,140.365 55.728,140.365 52.728,141.635 53.478,141.635 54.228,141.635 54.978,141.635 55.728,141.635 52.728,142.905 53.478,142.905 54.228,142.905 54.978,142.905 55.728,142.905 52.728,147.365 53.478,147.365 54.228,147.365 54.978,147.365 55.728,147.365 52.728,148.635 53.478,148.635 54.228,148.635 54.978,148.635 55.728,148.635 52.728,149.905 53.478,149.905 54.228,149.905 54.978,149.905 55.728,149.905 52.728,154.365 53.478,154.365 54.228,154.365 54.978,154.365 55.728,154.365 52.728,155.635 53.478,155.635 54.228,155.635 54.978,155.635 55.728,155.635 52.728,156.905 53.478,156.905 54.228,156.905 54.978,156.905 55.728,156.905 52.728,161.365 53.478,161.365 54.228,161.365 54.978,161.365 55.728,161.365 52.728,162.635 53.478,162.635 54.228,162.635 54.978,162.635 55.728,162.635 52.728,163.905 53.478,163.905 54.228,163.905 54.978,163.905 55.728,163.905
OUT_A3: C32A.2 P3.1 R45A.2 T4A.S T5A.S T6A.S U4A.23 | length 42.6
  Top Layer w0.3: v1(75,127) 75.095,127 75.345,126.75 U4A.23@76.848,126.75
  Bottom Layer w0.3: 50.5,105 53.5,105 54.25,105.75 54.5,106 66,106 69.5,109.5 69.5,116.5 70.804,117.804 70.804,120.554 74.125,123.875 74.125,126.125 v1(75,127)
  other v1: 49.728,109.365 50.478,109.365 51.228,109.365 51.978,109.365 52.728,109.365 49.728,110.635 50.478,110.635 51.228,110.635 51.978,110.635 52.728,110.635 49.728,111.905 50.478,111.905 51.228,111.905 51.978,111.905 52.728,111.905 49.728,116.365 50.478,116.365 51.228,116.365 51.978,116.365 52.728,116.365 49.728,117.635 50.478,117.635 51.228,117.635 51.978,117.635 52.728,117.635 49.728,118.905 50.478,118.905 51.228,118.905 51.978,118.905 52.728,118.905 49.728,123.365 50.478,123.365 51.228,123.365 51.978,123.365 52.728,123.365 49.728,124.635 50.478,124.635 51.228,124.635 51.978,124.635 52.728,124.635 49.728,125.905 50.478,125.905 51.228,125.905 51.978,125.905 52.728,125.905
OUT_A4: C32B.2 P4.1 R45B.2 T4B.S T5B.S T6B.S U4B.23 | length 24.6
  Top Layer w0.3: v1(69.25,79.425) 69.276,79.425 69.699,79.848 74.098,79.848 74.25,80 U4B.23@75.598,80
  Bottom Layer w0.3: 51.252,79.425 v1(69.25,79.425)
  other v1: 49.728,83.365 50.478,83.365 51.228,83.365 51.978,83.365 52.728,83.365 49.728,84.635 50.478,84.635 51.228,84.635 51.978,84.635 52.728,84.635 49.728,85.905 50.478,85.905 51.228,85.905 51.978,85.905 52.728,85.905 49.728,90.365 50.478,90.365 51.228,90.365 51.978,90.365 52.728,90.365 49.728,91.635 50.478,91.635 51.228,91.635 51.978,91.635 52.728,91.635 49.728,92.905 50.478,92.905 51.228,92.905 51.978,92.905 52.728,92.905 49.728,97.365 50.478,97.365 51.228,97.365 51.978,97.365 52.728,97.365 49.728,98.635 50.478,98.635 51.228,98.635 51.978,98.635 52.728,98.635 49.728,99.905 50.478,99.905 51.228,99.905 51.978,99.905 52.728,99.905
OUT_A5: C32C.2 P5.1 R45C.2 T4C.S T5C.S T6C.S U4C.23 | length 32.8
  Top Layer w0.3: v1(77,61.15) 77,61.25 77.75,62 U4C.23@79.848,62
  Bottom Layer w0.3: 51.5,53.5 70.884,53.5 77,59.616 v1(77,61.15)
  other v1: 49.728,57.365 50.478,57.365 51.228,57.365 51.978,57.365 52.728,57.365 49.728,58.635 50.478,58.635 51.228,58.635 51.978,58.635 52.728,58.635 49.728,59.905 50.478,59.905 51.228,59.905 51.978,59.905 52.728,59.905 49.728,64.365 50.478,64.365 51.228,64.365 51.978,64.365 52.728,64.365 49.728,65.635 50.478,65.635 51.228,65.635 51.978,65.635 52.728,65.635 49.728,66.905 50.478,66.905 51.228,66.905 51.978,66.905 52.728,66.905 49.728,71.365 50.478,71.365 51.228,71.365 51.978,71.365 52.728,71.365 49.728,72.635 50.478,72.635 51.228,72.635 51.978,72.635 52.728,72.635 49.728,73.905 50.478,73.905 51.228,73.905 51.978,73.905 52.728,73.905
OUT_A6: C7A.2 P6.1 U1A.6 U7A.11 | length 28.1
  Top Layer w0.3: U7A.11@80,101.098 80,98.25 80.95,97.3 84.55,97.3 94.475,107.225 P6.1@94.475,113.45
  other v1: 96.5,101 97.25,101 98,101 98.75,101 95.75,101.75 96.5,101.75 97.25,101.75 98,101.75 98.75,101.75 95.75,102.5 96.5,102.5 97.25,102.5 98,102.5 98.75,102.5
OUT_A7: C6A.2 P6.3 U1A.5 U7A.12 | length 37.6
  Top Layer w0.3: U7A.12@80.5,101.098 80.5,98.386 81.136,97.75 84.364,97.75 91.5,104.886 91.5,114 92.5,115 100.425,115 P6.3@101.975,113.45
  other v1: 100.25,101 101,101 101.75,101 102.5,101 100.25,101.75 101,101.75 101.75,101.75 102.5,101.75 103.25,101.75 100.25,102.5 101,102.5 101.75,102.5 102.5,102.5 103.25,102.5
OUT_A8: C7B.2 P6.5 U1B.6 U7A.14 | length 43
  Top Layer w0.3: U7A.14@81.5,101.098 81.5,99.55 82.3,98.75 84.727,98.75 90.75,104.773 90.75,114 92.25,115.5 107.425,115.5 P6.5@109.475,113.45
  other v1: 111.5,101 112.25,101 113,101 113.75,101 110.75,101.75 111.5,101.75 112.25,101.75 113,101.75 113.75,101.75 110.75,102.5 111.5,102.5 112.25,102.5 113,102.5 113.75,102.5
OUT_A9: C6B.2 P6.7 U1B.5 U7A.15 | length 49.8
  Top Layer w0.3: U7A.15@82,101.098 82,100.05 82.8,99.25 84.591,99.25 90,104.659 90,114 92,116 114.425,116 P6.7@116.975,113.45
  other v1: 115.25,101 116,101 116.75,101 117.5,101 115.25,101.75 116,101.75 116.75,101.75 117.5,101.75 118.25,101.75 115.25,102.5 116,102.5 116.75,102.5 117.5,102.5 118.25,102.5
OUT_A10: C22.2 P6.2 R114.1 U3.21 U3.22 | length 57.1
  Top Layer w0.3: R114.1@78.5,112.025 78.5,113.25 83.95,118.7 92.725,118.7 P6.2@94.475,120.45
  Top Layer w0.8: v1@102.223,135.723 v1(102.237,135.737) 102.25,135.75 U3.21@104.25,135.75
  Top Layer w1: P6.2@97,120.475 P6.2@97.025,120.45
  Top Layer w1.5: P6.2@97.025,120.45 97.025,130.525 99.25,132.75 v1(100.737,134.237) v1(101.5,135) v1@102.223,135.723
  Bottom Layer w1.5: P6.2@97.025,120.45 97.025,130.525 v1(100.737,134.237) v1(102.237,135.737)
OUT_A11: C21.2 P6.4 R113.1 U3.27 U3.28 | length 51.5
  Top Layer w0.3: R113.1@79.75,112.025 79.75,113.25 84.75,118.25 99.75,118.25 P6.4@101.975,120.475
  Top Layer w0.8: v1(105.513,131.263) 106.5,132.25 U3.27@106.5,133.5
  Top Layer w1.5: P6.4@104.525,120.475 104.525,129 104.525,130.275 v1(105.513,131.263)
  Bottom Layer w1.5: P6.4@104.525,120.475 104.525,130.275 v1(105.513,131.263)
  other v1: 104.5,129.5 104.75,130.5
OUT_A12: C20.2 P6.6 R112.1 U3.29 U3.30 | length 56.9
  Top Layer w0.3: R112.1@81.75,112.025 81.75,113 86.5,117.75 106.775,117.75 P6.6@109.475,120.45
  Top Layer w0.8: U3.29@107.5,133.5 107.5,132.25 v1(108.5,131.25)
  Top Layer w1.5: v1(108.5,131.25) 109.475,130.275 109.475,129.5 109.475,129 P6.6@109.475,120.45
  Bottom Layer w1.5: v1(108.5,131.25) 109.475,130.275 P6.6@109.475,120.45
  other v1: 109.5,129.5 109.25,130.5
OUT_A13: C23.2 P6.8 R111.1 U3.3 U3.4 | length 74.4
  Top Layer w0.3: R111.1@83,112.025 83.025,112.025 83.325,112.325 83.325,112.35 88.225,117.25 113.775,117.25 P6.8@116.975,120.45
  Top Layer w0.8: U3.3@109.75,135.75 v1(111.75,135.75)
  Top Layer w1.5: v1(111.75,135.75) v1(111.75,134.75) 111.75,125.675 P6.8@116.975,120.45
  Bottom Layer w1.5: v1(111.75,135.75) 111.75,125.675 P6.8@116.975,120.45
  other v1: 111.75,133.75
OUT_B1: C42B.2 P7.1 R64B.2 T7B.S T8B.S T9B.S T10B.S T11B.S T12B.S T13B.S T14B.S Tr_d10.A U5B.23 | length 57.2
  Top Layer w0.2: U5B.23@157.902,194 159,194
  Top Layer w0.3: 159,194 159.4,194 v1(160.25,194.85)
  Bottom Layer w0.3: v1(160.25,194.85) 160.25,196 160.249,196.249 171.75,207.75 171.75,214.5 180.75,223.5 196,223.5 197.469,222.031
  other v1: 194.272,168.095 195.022,168.095 195.772,168.095 196.522,168.095 197.272,168.095 194.272,169.365 195.022,169.365 195.772,169.365 196.522,169.365 197.272,169.365 194.272,170.635 195.022,170.635 195.772,170.635 196.522,170.635 197.272,170.635 194.272,175.095 195.022,175.095 195.772,175.095 196.522,175.095 197.272,175.095 194.272,176.365 195.022,176.365 195.772,176.365 196.522,176.365 197.272,176.365 194.272,177.635 195.022,177.635 195.772,177.635 196.522,177.635 197.272,177.635 194.272,182.095 195.022,182.095 195.772,182.095 196.522,182.095 197.272,182.095 194.272,183.365 195.022,183.365 195.772,183.365 196.522,183.365 197.272,183.365 194.272,184.635 195.022,184.635 195.772,184.635 196.522,184.635 197.272,184.635 194.272,189.095 195.022,189.095 195.772,189.095 196.522,189.095 197.272,189.095 194.272,190.365 195.022,190.365 195.772,190.365 196.522,190.365 197.272,190.365 194.272,191.635 195.022,191.635 195.772,191.635 196.522,191.635 197.272,191.635 194.272,196.095 195.022,196.095 195.772,196.095 196.522,196.095 197.272,196.095 194.272,197.365 195.022,197.365 195.772,197.365 196.522,197.365 197.272,197.365 194.272,198.635 195.022,198.635 195.772,198.635 196.522,198.635 197.272,198.635 194.272,203.095 195.022,203.095 195.772,203.095 196.522,203.095 197.272,203.095 194.272,204.365 195.022,204.365 195.772,204.365 196.522,204.365 197.272,204.365 194.272,205.635 195.022,205.635 195.772,205.635 196.522,205.635 197.272,205.635 194.272,210.095 195.022,210.095 195.772,210.095 196.522,210.095 197.272,210.095 194.272,211.365 195.022,211.365 195.772,211.365 196.522,211.365 197.272,211.365 194.272,212.635 195.022,212.635 195.772,212.635 196.522,212.635 197.272,212.635 194.272,217.095 195.022,217.095 195.772,217.095 196.522,217.095 197.272,217.095 194.272,218.365 195.022,218.365 195.772,218.365 196.522,218.365 197.272,218.365 194.272,219.635 195.022,219.635 195.772,219.635 196.522,219.635 197.272,219.635
OUT_B2: C52B.2 P8.1 R84B.2 T15B.S T16B.S T17B.S T18B.S T19B.S Tr_d13.A U6B.23 | length 39.7
  Top Layer w0.3: U6B.23@161.402,140.25 163.439,140.25 163.749,140.56 168.96,140.56 v1(170.01,139.51)
  Bottom Layer w0.3: v1(170.01,139.51) 179.77,129.75 194.75,129.75 196,131
  other v1: 194.272,132.095 195.022,132.095 195.772,132.095 196.522,132.095 197.272,132.095 194.272,133.365 195.022,133.365 195.772,133.365 196.522,133.365 197.272,133.365 194.272,134.635 195.022,134.635 195.772,134.635 196.522,134.635 197.272,134.635 194.272,139.095 195.022,139.095 195.772,139.095 196.522,139.095 197.272,139.095 194.272,140.365 195.022,140.365 195.772,140.365 196.522,140.365 197.272,140.365 194.272,141.635 195.022,141.635 195.772,141.635 196.522,141.635 197.272,141.635 194.272,146.095 195.022,146.095 195.772,146.095 196.522,146.095 197.272,146.095 194.272,147.365 195.022,147.365 195.772,147.365 196.522,147.365 197.272,147.365 194.272,148.635 195.022,148.635 195.772,148.635 196.522,148.635 197.272,148.635 194.272,153.095 195.022,153.095 195.772,153.095 196.522,153.095 197.272,153.095 194.272,154.365 195.022,154.365 195.772,154.365 196.522,154.365 197.272,154.365 194.272,155.635 195.022,155.635 195.772,155.635 196.522,155.635 197.272,155.635 194.272,160.095 195.022,160.095 195.772,160.095 196.522,160.095 197.272,160.095 194.272,161.365 195.022,161.365 195.772,161.365 196.522,161.365 197.272,161.365 194.272,162.635 195.022,162.635 195.772,162.635 196.522,162.635 197.272,162.635
OUT_B3: C32D.2 P9.1 R45D.2 T4D.S T5D.S T6D.S U4D.23 | length 35.6
  Top Layer w0.3: U4D.23@170.152,120 172.25,120 173,120.75 v1(173,120.85)
  Bottom Layer w0.3: 199.75,128.5 179.116,128.5 173,122.384 ; 173,122.384 v1(173,120.85) 173,122.384
  other v1: 197.272,107.595 198.022,107.595 198.772,107.595 199.522,107.595 200.272,107.595 197.272,108.865 198.022,108.865 198.772,108.865 199.522,108.865 200.272,108.865 197.272,110.135 198.022,110.135 198.772,110.135 199.522,110.135 200.272,110.135 197.272,114.595 198.022,114.595 198.772,114.595 199.522,114.595 200.272,114.595 197.272,115.865 198.022,115.865 198.772,115.865 199.522,115.865 200.272,115.865 197.272,117.135 198.022,117.135 198.772,117.135 199.522,117.135 200.272,117.135 197.272,121.595 198.022,121.595 198.772,121.595 199.522,121.595 200.272,121.595 197.272,122.865 198.022,122.865 198.772,122.865 199.522,122.865 200.272,122.865 197.272,124.135 198.022,124.135 198.772,124.135 199.522,124.135 200.272,124.135
OUT_B4: C32E.2 P10.1 R45E.2 T4E.S T5E.S T6E.S U4E.23 | length 34.1
  Top Layer w0.3: U4E.23@170.152,94 172.25,94 173,94.75 v1(173,94.85)
  Bottom Layer w0.3: v1(173,94.85) 173,96.5 173.5,97 178,97 183.5,102.5 199.75,102.5
  other v1: 197.272,81.595 198.022,81.595 198.772,81.595 199.522,81.595 200.272,81.595 197.272,82.865 198.022,82.865 198.772,82.865 199.522,82.865 200.272,82.865 197.272,84.135 198.022,84.135 198.772,84.135 199.522,84.135 200.272,84.135 197.272,88.595 198.022,88.595 198.772,88.595 199.522,88.595 200.272,88.595 197.272,89.865 198.022,89.865 198.772,89.865 199.522,89.865 200.272,89.865 197.272,91.135 198.022,91.135 198.772,91.135 199.522,91.135 200.272,91.135 197.272,95.595 198.022,95.595 198.772,95.595 199.522,95.595 200.272,95.595 197.272,96.865 198.022,96.865 198.772,96.865 199.522,96.865 200.272,96.865 197.272,98.135 198.022,98.135 198.772,98.135 199.522,98.135 200.272,98.135
OUT_B5: C32F.2 P11.1 R45F.2 T4F.S T5F.S T6F.S U4F.23 | length 34.1
  Top Layer w0.3: U4F.23@170.152,68 172.25,68 173,68.75 v1(173,68.85)
  Bottom Layer w0.3: v1(173,68.85) 173,70.5 173.5,71 178,71 183.5,76.5 199.75,76.5
  other v1: 197.272,55.595 198.022,55.595 198.772,55.595 199.522,55.595 200.272,55.595 197.272,56.865 198.022,56.865 198.772,56.865 199.522,56.865 200.272,56.865 197.272,58.135 198.022,58.135 198.772,58.135 199.522,58.135 200.272,58.135 197.272,62.595 198.022,62.595 198.772,62.595 199.522,62.595 200.272,62.595 197.272,63.865 198.022,63.865 198.772,63.865 199.522,63.865 200.272,63.865 197.272,65.135 198.022,65.135 198.772,65.135 199.522,65.135 200.272,65.135 197.272,69.595 198.022,69.595 198.772,69.595 199.522,69.595 200.272,69.595 197.272,70.865 198.022,70.865 198.772,70.865 199.522,70.865 200.272,70.865 197.272,72.135 198.022,72.135 198.772,72.135 199.522,72.135 200.272,72.135
OUT_B6: C7C.2 P12.1 U1C.6 U7B.11 | length 24.4
  Top Layer w0.3: P12.1@146.038,161.515 148.765,161.515 152.5,165.25 152.5,166.75 156.45,170.7 161.55,170.7 162.5,169.75 U7B.11@162.5,166.902
  other v1: 141.75,172.5 141.75,172.5 142.5,172.5 142.5,172.5 143.25,172.5 143.25,172.5 144,172.5 144,172.5 144.75,172.5 144.75,172.5 141.75,173.25 141.75,173.25 142.5,173.25 142.5,173.25 143.25,173.25 143.25,173.25 144,173.25 144,173.25 144.75,173.25 144.75,173.25 141.75,174 141.75,174 142.5,174 142.5,174 143.25,174 143.25,174 144,174 144,174
OUT_B7: C6C.2 P12.3 U1C.5 U7B.12 | length 32.4
  Top Layer w0.3: P12.3@138.538,161.515 140.303,159.75 147.75,159.75 153,165 153,166.5 156.75,170.25 161.364,170.25 162,169.614 U7B.12@162,166.902
  other v1: 137.25,172.5 137.25,172.5 138,172.5 138,172.5 138.75,172.5 138.75,172.5 139.5,172.5 139.5,172.5 140.25,172.5 140.25,172.5 137.25,173.25 137.25,173.25 138,173.25 138,173.25 138.75,173.25 138.75,173.25 139.5,173.25 139.5,173.25 140.25,173.25 140.25,173.25 138,174 138,174 138.75,174 138.75,174 139.5,174 139.5,174 140.25,174 140.25,174
OUT_B8: C7D.2 P12.5 U1D.6 U7B.14 | length 37.8
  Top Layer w0.3: P12.5@131.038,161.515 133.303,159.25 148,159.25 153.5,164.75 153.5,166.25 156.5,169.25 160.2,169.25 161,168.45 U7B.14@161,166.902
  other v1: 126.75,172.5 127.5,172.5 128.25,172.5 129,172.5 129.75,172.5 126.75,173.25 127.5,173.25 128.25,173.25 129,173.25 129.75,173.25 126.75,174 127.5,174 128.25,174 129,174
OUT_B9: C6D.2 P12.7 U1D.5 U7B.15 | length 44.5
  Top Layer w0.3: P12.7@123.538,161.515 126.303,158.75 148.25,158.75 154.075,164.575 154.075,166.075 156.75,168.75 159.7,168.75 160.5,167.95 U7B.15@160.5,166.902
  other v1: 122.25,172.5 123,172.5 123.75,172.5 124.5,172.5 125.25,172.5 122.25,173.25 123,173.25 123.75,173.25 124.5,173.25 125.25,173.25 123,174 123.75,174 124.5,174 125.25,174
OUT_B10: C13A.2 P12.2 R118.1 U2A.21 U2A.22 U2A.23 U2A.24 | length 19.1
  Top Layer w0.3: P12.2@146.038,154.515 148.735,154.515 149.25,154 162.25,154 163.675,155.425 163.675,155.675 163.975,155.975 R118.1@164,155.975
  other v3: 144.5,141.5 145.25,141.5 144.5,142.25 145.25,142.25 146,142.25 144.5,143 145.25,143 146,143
OUT_B11: C14A.2 P12.4 R117.1 U2A.1 U2A.2 U2A.3 U2A.4 | length 26.5
  Top Layer w0.3: P12.4@138.538,154.49 140.299,156.25 147.75,156.25 149.5,154.5 161.75,154.5 162.5,155.25 R117.1@162.5,155.975
  other v3: 136.75,141.5 137.5,141.5 136,142.25 136.75,142.25 137.5,142.25 136,143 136.75,143 137.5,143
OUT_B12: C13B.2 P12.6 R116.1 U2B.21 U2B.22 U2B.23 U2B.24 | length 32.4
  Top Layer w0.3: P12.6@131.038,154.515 133.274,156.75 148,156.75 149.75,155 160.5,155 160.925,155.425 160.925,155.675 161.225,155.975 R116.1@161.25,155.975
  other v3: 129.5,141.5 130.25,141.5 129.5,142.25 130.25,142.25 131,142.25 129.5,143 130.25,143 131,143
OUT_B13: C14B.2 P12.8 R115.1 U2B.1 U2B.2 U2B.3 U2B.4 | length 38.1
  Top Layer w0.3: P12.8@123.538,154.515 126.274,157.25 148.25,157.25 149.525,155.975 R115.1@160,155.975
  other v3: 121.75,141.5 122.5,141.5 121,142.25 121.75,142.25 122.5,142.25 121,143 121.75,143 122.5,143
OUTST_A1: R80A.2 U8.31 | length 187.7
  Top Layer w0.2: R80A.2@104.775,199.5 106.75,199.5 112,194.25 112,159 116.083,154.917 116.083,149.757 119,146.84 119,130 128.48,120.52 128.48,94.52 132.75,90.25 v1(132.75,80.5) ; v1(115.25,37.25) 117.01,37.25 U8.31@118.682,38.922
  Layer 1 w0.5: v1(115.25,37.25) 114.3,38.2 114.3,45.527 116.795,48.022 116.795,48.671 125.124,57 126,57 126.247,57.247 126.27,57.247 128.5,59.477 128.5,59.5 130,61 130,72 132.75,74.75 v1(132.75,80.5)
